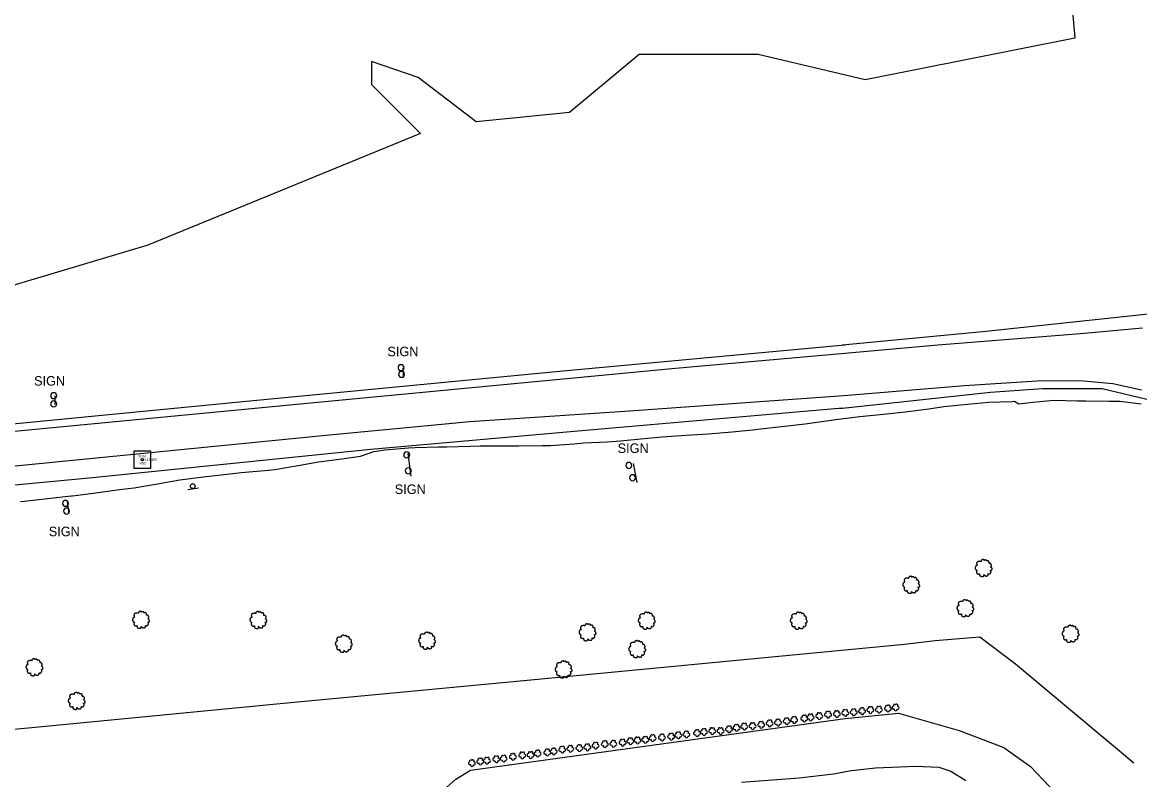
# Model space of a CAD drawing. Extents: x 1901471 to 1963503, y 756461 to 799997.
# Drawn here: x 1911553.6 to 1912023.9, y 761022.6 to 761341.4 of the extents above; entities that cross this region are included whole.
import ezdxf

# ---------------------------------------------------------------- set-up
doc = ezdxf.new("R2010")
doc.units = 0
for name, color, linetype in [('Default', 7, 'Continuous'), ('RD_DTM_BkLn1', 7, 'Continuous'), ('RD_EX_Bldg', 7, 'Continuous'), ('RD_EX_BldgApp', 7, 'Continuous'), ('RD_EX_Fence_Other', 7, 'Continuous'), ('RD_EX_H2O', 7, 'Continuous'), ('RD_EX_Road', 7, 'Continuous'), ('RD_EX_Road_txCode', 7, 'Continuous'), ('RD_EX_VEG', 7, 'Continuous'), ('RD_HC_Cl', 7, 'Continuous'), ('RD_HC_Survey', 7, 'Continuous'), ('RD_HC_txCode', 7, 'Continuous'), ('RD_SMD_Locator', 7, 'Continuous')]:
    doc.layers.add(name, color=color, linetype=linetype)

# ---------------------------------------------------------------- blocks, each defined once
blk = doc.blocks.new('T2')
at = {"layer": 'RD_EX_VEG'}
for points in [[(0.05, 7.21), (-0.25, 7.24), (-0.57, 7.14), (-0.82, 7.04), (-1.05, 6.96), (-1.27, 6.86), (-1.57, 6.69), (-1.8, 6.49), (-1.92, 6.24), (-1.97, 6.01), (-2.02, 5.74), (-2.02, 5.56), (-2.15, 5.54), (-2.3, 5.56), (-2.55, 5.64), (-2.8, 5.64), (-3.05, 5.64), (-3.4, 5.61), (-3.75, 5.61), (-4.02, 5.56), (-4.35, 5.51), (-4.72, 5.39), (-5.07, 5.26), (-5.37, 5.01), (-5.62, 4.54), (-5.75, 4.19), (-5.9, 3.94), (-5.75, 3.49), (-5.57, 3.14), (-5.55, 2.94), (-5.47, 2.52), (-5.37, 2.29), (-5.25, 2.09), (-5.32, 2.07), (-5.7, 2.02), (-6, 1.92), (-6.42, 1.69), (-6.64, 1.47), (-6.74, 1.14), (-6.77, 0.79), (-6.87, 0.59), (-6.94, 0.32), (-6.97, 0.24), (-7.02, -0.08), (-6.92, -0.53), (-6.89, -0.88), (-6.77, -1.11), (-6.62, -1.28), (-6.44, -1.53), (-6.05, -1.76), (-5.72, -1.86), (-5.52, -1.88), (-5.7, -2.38), (-5.75, -2.73), (-5.87, -3.13), (-5.87, -3.21), (-5.92, -3.68), (-5.77, -4.01), (-5.7, -4.38), (-5.52, -4.61), (-5.25, -4.91), (-4.92, -5.13), (-4.42, -5.26), (-4.02, -5.23), (-3.45, -5.06), (-3.2, -4.98), (-3.22, -5.16), (-3.2, -5.53), (-3.2, -5.96), (-3.05, -6.28), (-2.95, -6.56), (-2.8, -6.81), (-2.47, -7.03), (-2.07, -7.11), (-1.65, -7.26), (-1.2, -7.33), (-0.7, -7.36), (-0.1, -7.21), (0.18, -7.08), (0.28, -6.91), (0.48, -6.53), (0.43, -6.31), (0.45, -5.71), (0.55, -5.88), (0.73, -6.23), (1.23, -6.53), (1.63, -6.71), (2.1, -6.86), (2.4, -6.93), (2.88, -6.86), (3.25, -6.78), (3.63, -6.66), (3.93, -6.38), (4.1, -6.11), (4.15, -5.83), (4.23, -5.46), (4.28, -5.28)], [(4.28, -5.28), (4.2, -5.11), (4.15, -4.86), (4.23, -4.88), (4.4, -4.93), (4.68, -5.06), (4.9, -5.13), (5.23, -5.11), (5.5, -5.01), (5.95, -4.73), (6.22, -4.26), (6.5, -3.86), (6.57, -3.53), (6.52, -3.31), (6.5, -2.81), (6.3, -2.56), (6.25, -2.43), (6.15, -2.03), (6.22, -1.98), (6.5, -1.93), (6.87, -1.81), (7.15, -1.68), (7.37, -1.51), (7.45, -1.28), (7.42, -0.88), (7.47, -0.48), (7.4, -0.33), (7.3, -0.18), (7.22, 0.02), (7.07, 0.17), (6.97, 0.32), (6.87, 0.42), (6.75, 0.57), (6.57, 0.69), (6.42, 0.74), (6.37, 0.89), (6.52, 1.09), (6.57, 1.19), (6.6, 1.42), (6.82, 1.77), (6.87, 2.17), (6.82, 2.59), (6.77, 2.87), (6.62, 3.14), (6.42, 3.39), (6.3, 3.56), (6.12, 3.69), (5.8, 3.81), (5.55, 3.86), (5.2, 3.86), (5, 3.91), (5.03, 3.96), (5.03, 4.11), (5.03, 4.39), (4.95, 4.84), (4.8, 5.34), (4.8, 5.36), (4.7, 5.61), (4.48, 5.81), (4.3, 5.91), (4.1, 6.04), (3.85, 6.06), (3.55, 6.06), (3.28, 6.01), (3.08, 5.91), (2.9, 5.79), (2.83, 5.94), (2.73, 6.24), (2.68, 6.39), (2.53, 6.56), (2.3, 6.76), (1.85, 6.89), (1.23, 6.81), (0.93, 6.61), (0.78, 6.44), (0.73, 6.56), (0.53, 6.76), (0.43, 6.94), (0.25, 7.06), (0.1, 7.16), (0, 7.21)]]:
    blk.add_spline(points, degree=3, dxfattribs=at)
blk = doc.blocks.new('SB2')
at = {"layer": 'RD_EX_VEG'}
for centre, radius, start, end in [((-1.56, -0.16), 1.26, 96.45179, 294.73401), ((-0.72, 1.55), 1.08, 34.97629, 204.75602), ((1.05, 1.7), 0.995, 308.76261, 152.04674), ((1.84, -0.28), 1.22, 256.56668, 98.10463), ((0.25, -1.6), 1.32, 166.88266, 5.75893)]:
    blk.add_arc(centre, radius, start, end, dxfattribs=at)
blk = doc.blocks.new('SIGNPOST')
at = {"layer": 'Default'}
for start, end in [(90, 270), (270, 90)]:
    blk.add_arc((0, 0), 0.127, start, end, dxfattribs=at)
blk = doc.blocks.new('SIGN')
at = {"layer": 'RD_EX_BldgApp'}
blk.add_line((-4.52, -2.02), (4.48, -2.02), dxfattribs=at)
blk.add_circle((0, 0), 2, dxfattribs=at)

msp = doc.modelspace()

# ---------------------------------------------------------------- linework, layer by layer
at = {"layer": 'RD_DTM_BkLn1'}
for points in [[(1911659.88, 761153.18), (1911669.72, 761154.91), (1911678.21, 761156.4), (1911688.12, 761157.71), (1911695.98, 761158.75), (1911701.62, 761160.74), (1911706.22, 761161.47), (1911716.18, 761162.29), (1911718.95, 761162.52), (1911728.94, 761162.72), (1911732.15, 761162.78), (1911742.13, 761163.08), (1911746.35, 761163.21), (1911756.35, 761163.2), (1911762.54, 761163.2), (1911772.54, 761163.27), (1911775.88, 761163.29), (1911785.84, 761164.06), (1911789.81, 761164.36), (1911799.79, 761164.91), (1911805.35, 761165.22), (1911815.29, 761166.22), (1911822.91, 761167), (1911832.88, 761167.6), (1911842.39, 761168.18), (1911852.34, 761169.11), (1911862.29, 761170.03), (1911863.21, 761170.12), (1911873.14, 761171.31), (1911883.06, 761172.49), (1911886.06, 761172.85), (1911895.96, 761174.2), (1911906.1, 761175.58), (1911916.05, 761176.55), (1911925.23, 761177.45), (1911935.12, 761178.81), (1911941.43, 761179.67), (1911951.37, 761180.64), (1911960.3, 761181.51), (1911970.29, 761181.89), (1911971.21, 761181.93), (1911973.03, 761180.8), (1911978.98, 761181.5), (1911987.81, 761182.35), (1911997.8, 761182.16), (1912001.19, 761182.1), (1912011.18, 761182.03), (1912015.59, 761181.99), (1912024.5, 761180.87)], [(1911552.87, 761139.7), (1911554.34, 761139.87), (1911564.26, 761140.99), (1911574.19, 761142.1), (1911574.69, 761142.15), (1911584.59, 761143.44), (1911594.5, 761144.72), (1911600.71, 761145.53), (1911610.55, 761147.23), (1911619.95, 761148.86), (1911629.87, 761150.07), (1911639.79, 761151.29), (1911645.68, 761152.01), (1911655.63, 761152.83), (1911659.88, 761153.18)]]:
    msp.add_lwpolyline(points, dxfattribs=at)
at = {"layer": 'RD_EX_Bldg'}
for points in [[(1911714.11, 761192.5), (1911713.9, 761195.96)], [(1911567.49, 761180.52), (1911567.49, 761184.19)], [(1911717.35, 761150.39), (1911716.06, 761159.89)], [(1911812.36, 761147.8), (1911810.85, 761155.79)], [(1911573.32, 761134.63), (1911572.67, 761139.6)]]:
    msp.add_lwpolyline(points, dxfattribs=at)
at = {"layer": 'RD_EX_Fence_Other'}
for points in [[(1911301.9, 761016.76), (1911361.19, 761026.56), (1911419.09, 761032.24), (1911466.66, 761036.35), (1911557.62, 761044.66), (1911663.61, 761054.89), (1911770.66, 761064.95), (1911924.93, 761079.73), (1911937.87, 761081.21), (1911956.59, 761082.79), (1911971.63, 761071.42), (1912021.48, 761029.79)], [(1911763.4, 760914.3), (1911750.84, 760916.21), (1911744.62, 760921.26), (1911722.85, 760995.7), (1911722.85, 761003.37), (1911725.57, 761010.56), (1911730.04, 761017.56), (1911736.07, 761022.81), (1911742.29, 761026.69), (1911899.9, 761048.36), (1911922.46, 761050.69), (1911947.94, 761043.35), (1911966.73, 761036.22), (1911977.96, 761028.23), (1911993.72, 761011.61), (1911997.39, 761002.75), (1911997.82, 760995.2), (1911994.8, 760987.64), (1911989.62, 760981.81), (1911983.14, 760977.27), (1911976.23, 760974.03), (1911966.94, 760971.23), (1911949.45, 760965.61), (1911905.83, 760953.84)]]:
    msp.add_lwpolyline(points, dxfattribs=at)
at = {"layer": 'RD_EX_H2O'}
msp.add_lwpolyline([(1911856.34, 761021.65), (1911880.53, 761023.47), (1911895.01, 761025.08), (1911901.72, 761026.38), (1911902.64, 761026.54), (1911912.73, 761027.6), (1911929.56, 761028.37), (1911939.37, 761027.86), (1911944.43, 761026.16), (1911950.75, 761022.26)], dxfattribs=at)
at = {"layer": 'RD_EX_Road'}
for points in [[(1912072.27, 761284.55), (1912073.94, 761249.92), (1912071.95, 761235.72), (1912064.97, 761228.49), (1912046.04, 761220.52), (1911959.1, 761211.3), (1911898.88, 761205.6)], [(1910806.95, 760986.51), (1910899.81, 761023.81), (1910997.7, 761062.68), (1911080.96, 761091.36), (1911138.06, 761108.15), (1911210.76, 761126.27), (1911274.58, 761138.02), (1911355.92, 761149.66), (1911431.5, 761158.3), (1911541.39, 761168.49), (1911685.34, 761182.29), (1911828.58, 761195.85), (1911899.84, 761202.2), (1911938.91, 761205.69), (1911998.94, 761210.45), (1912025.07, 761212.82)], [(1910882.79, 761021.04), (1910921.3, 761035.52), (1910979.88, 761059.55), (1911049, 761083.58), (1911113.18, 761104.97), (1911182.95, 761123.73), (1911238.25, 761135.74), (1911300.45, 761145.95), (1911367.92, 761154.5), (1911431.77, 761161.25), (1911532.15, 761170.79), (1911649.32, 761182.15), (1911779.66, 761194.66), (1911899.79, 761205.68)], [(1910585.74, 760878.06), (1910710.5, 760928.56), (1910888.29, 761001.62), (1910940.6, 761022.74), (1910979.47, 761037.97), (1911045.69, 761063.88), (1911129.18, 761091.6), (1911194.2, 761107.91), (1911276.02, 761125.07), (1911337.2, 761133.46), (1911445.17, 761144.38), (1911566.34, 761156.26), (1911684.38, 761167.89), (1911741.97, 761173.41), (1911807.23, 761177.73), (1911899.39, 761184.42), (1911950.14, 761188.53), (1911980.8, 761190.47), (1911998.72, 761190.69), (1912012.54, 761189.39), (1912024.63, 761186.8)], [(1911897.49, 761178.91), (1911961.09, 761185.77), (1911983.01, 761187.26), (1912008.17, 761187.26), (1912029.35, 761182.28), (1912048.28, 761172.06), (1912063.23, 761159.36), (1912077.93, 761137.06), (1912083.66, 761120.12), (1912085.9, 761099.07), (1912090.39, 761029.31), (1912094.37, 760970.15), (1912097.86, 760918.95), (1912097.86, 760912.35), (1912095.12, 760847.08), (1912093.87, 760825.28), (1912094.12, 760802.11), (1912094.28, 760797.36)], [(1911898.8, 761179.02), (1911785.91, 761169.15), (1911700.34, 761161.58), (1911583.17, 761149.73), (1911418.28, 761134.1), (1911324.15, 761123.73), (1911252.4, 761112.21), (1911180.98, 761095.75), (1911047.68, 761055.44), (1910980.21, 761027.79), (1910849.63, 760977.02), (1910755.82, 760938.15), (1910677.81, 760906.77), (1910499.57, 760835.69), (1910338.5, 760760.54), (1910201.4, 760696.87), (1909857.87, 760545.92), (1909713.02, 760487.06), (1909551.94, 760422.89), (1909472.41, 760392.45), (1909224.63, 760297.56), (1909135.34, 760263.39), (1909100.59, 760249.47)]]:
    msp.add_lwpolyline(points, dxfattribs=at)
at = {"layer": 'RD_EX_VEG'}
msp.add_lwpolyline([(1911365.4, 761253.45), (1911526.14, 761364.2), (1911737.84, 761511.22), (1911890.73, 761612.17), (1911939.74, 761640.59), (1911963.26, 761618.05), (1911978.94, 761536.7), (1911996.58, 761334.8), (1911908.37, 761317.16), (1911863.29, 761327.94), (1911813.31, 761327.94), (1911783.9, 761303.44), (1911744.7, 761299.52), (1911720.2, 761318.14), (1911700.59, 761325), (1911700.59, 761315.2), (1911721.18, 761294.61), (1911606.51, 761247.57), (1911550.64, 761230.91), (1911510.46, 761233.85), (1911426.17, 761216.21), (1911373.24, 761194.64), (1911348.74, 761205.43), (1911355.6, 761230.91)], close=True, dxfattribs=at)
at = {"layer": 'RD_HC_Cl'}
for centre, radius, start, end in [((1905408.25, 771170.65), 11414.07, 290.89447, 304.008825), ((1905390.19, 771086.47), 11384.37, 290.903407, 304.008529), ((1905358.49, 771272.41), 11611.54, 290.901971, 304.0171)]:
    msp.add_arc(centre, radius, start, end, dxfattribs=at)
at = {"layer": 'RD_HC_Survey'}
msp.add_lwpolyline([(1911607.68, 761160.89), (1911600.61, 761160.89), (1911600.61, 761153.81), (1911607.68, 761153.81)], close=True, dxfattribs=at)
msp.add_circle((1911604.14, 761157.35), 0.5, dxfattribs=at)
at = {"layer": 'RD_SMD_Locator'}
msp.add_circle((1911604.14, 761157.35), 0.001, dxfattribs=at)

# ---------------------------------------------------------------- block references
at = {"layer": 'RD_EX_Bldg', "xscale": 9.84251968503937, "yscale": 9.84251968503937}
for p in [(1911713.03, 761196.06), (1911713.25, 761193.26), (1911566.84, 761184.29), (1911566.84, 761180.84), (1911715.41, 761159.35), (1911808.91, 761154.93), (1911716.06, 761152.66), (1911810.42, 761149.74), (1911571.81, 761138.95), (1911572.24, 761135.71)]:
    msp.add_blockref('SIGNPOST', p, dxfattribs=at)
at = {"layer": 'RD_EX_Bldg', "xscale": 0.5039370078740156, "yscale": 0.5039370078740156, "rotation": 9.293309}
msp.add_blockref('SIGN', (1911625.36, 761146.18), dxfattribs=at)
at = {"layer": 'RD_EX_VEG'}
for name, p, xscale, yscale in [('T2', (1911958.11, 761111.77), 0.4921259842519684, 0.4921259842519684), ('T2', (1911927.66, 761104.7), 0.4921259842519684, 0.4921259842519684), ('T2', (1911950.42, 761094.86), 0.4921259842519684, 0.4921259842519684), ('T2', (1911603.46, 761089.97), 0.4921259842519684, 0.4921259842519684), ('T2', (1911652.86, 761089.89), 0.4921259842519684, 0.4921259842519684), ('T2', (1911816.32, 761089.63), 0.4921259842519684, 0.4921259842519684), ('T2', (1911880.29, 761089.63), 0.4921259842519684, 0.4921259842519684), ('T2', (1911723.87, 761081.17), 0.4921259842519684, 0.4921259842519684), ('T2', (1911791.41, 761084.71), 0.4921259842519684, 0.4921259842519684), ('T2', (1911994.71, 761084.09), 0.4921259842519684, 0.4921259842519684), ('T2', (1911688.81, 761079.89), 0.4921259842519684, 0.4921259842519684), ('T2', (1911812.32, 761077.63), 0.4921259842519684, 0.4921259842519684), ('T2', (1911558.6, 761070), 0.4921259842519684, 0.4921259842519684), ('T2', (1911781.33, 761069.08), 0.4921259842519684, 0.4921259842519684), ('T2', (1911576.4, 761055.83), 0.4921259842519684, 0.4921259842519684), ('SB2', (1911892.7, 761050.07), 0.5019685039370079, 0.5019685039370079), ('SB2', (1911896.36, 761050.3), 0.5019685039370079, 0.5019685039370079), ('SB2', (1911899.89, 761050.78), 0.5019685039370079, 0.5019685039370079), ('SB2', (1911903.48, 761051.05), 0.5019685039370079, 0.5019685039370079), ('SB2', (1911907, 761051.52), 0.5019685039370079, 0.5019685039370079), ('SB2', (1911910.52, 761052), 0.5019685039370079, 0.5019685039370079), ('SB2', (1911914.12, 761052.2), 0.5019685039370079, 0.5019685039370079), ('SB2', (1911917.84, 761052.67), 0.5019685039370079, 0.5019685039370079), ('SB2', (1911921.1, 761053.08), 0.5019685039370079, 0.5019685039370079), ('SB2', (1911857.4, 761045.05), 0.5019685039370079, 0.5019685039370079), ('SB2', (1911860.92, 761045.25), 0.5019685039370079, 0.5019685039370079), ('SB2', (1911864.51, 761045.8), 0.5019685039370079, 0.5019685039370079), ('SB2', (1911868.1, 761046.41), 0.5019685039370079, 0.5019685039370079), ('SB2', (1911871.63, 761046.74), 0.5019685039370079, 0.5019685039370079), ('SB2', (1911875.29, 761047.29), 0.5019685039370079, 0.5019685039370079), ('SB2', (1911878.4, 761047.83), 0.5019685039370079, 0.5019685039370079), ('SB2', (1911882.67, 761048.44), 0.5019685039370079, 0.5019685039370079), ('SB2', (1911885.32, 761048.91), 0.5019685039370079, 0.5019685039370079), ('SB2', (1911888.98, 761049.46), 0.5019685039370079, 0.5019685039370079), ('SB2', (1911822.77, 761040.44), 0.5019685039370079, 0.5019685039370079), ('SB2', (1911826.63, 761040.78), 0.5019685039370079, 0.5019685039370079), ('SB2', (1911829.61, 761041.39), 0.5019685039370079, 0.5019685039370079), ('SB2', (1911833.07, 761041.73), 0.5019685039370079, 0.5019685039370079), ('SB2', (1911837.54, 761042.27), 0.5019685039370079, 0.5019685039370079), ('SB2', (1911840.46, 761042.75), 0.5019685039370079, 0.5019685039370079), ('SB2', (1911843.91, 761043.15), 0.5019685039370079, 0.5019685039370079), ('SB2', (1911847.44, 761043.15), 0.5019685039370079, 0.5019685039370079), ('SB2', (1911851.03, 761043.9), 0.5019685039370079, 0.5019685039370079), ('SB2', (1911854.15, 761044.51), 0.5019685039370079, 0.5019685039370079), ('SB2', (1911784.21, 761035.7), 0.5019685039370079, 0.5019685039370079), ('SB2', (1911788.01, 761035.97), 0.5019685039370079, 0.5019685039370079), ('SB2', (1911791.4, 761036.31), 0.5019685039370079, 0.5019685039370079), ('SB2', (1911794.85, 761037.05), 0.5019685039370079, 0.5019685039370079), ('SB2', (1911798.71, 761037.66), 0.5019685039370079, 0.5019685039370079), ('SB2', (1911802.31, 761037.8), 0.5019685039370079, 0.5019685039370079), ('SB2', (1911806.17, 761038.27), 0.5019685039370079, 0.5019685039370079), ('SB2', (1911809.49, 761038.88), 0.5019685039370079, 0.5019685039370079), ('SB2', (1911812.47, 761039.22), 0.5019685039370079, 0.5019685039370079), ('SB2', (1911815.72, 761039.49), 0.5019685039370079, 0.5019685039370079), ('SB2', (1911818.84, 761040.17), 0.5019685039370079, 0.5019685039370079), ('SB2', (1911753.04, 761031.29), 0.5019685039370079, 0.5019685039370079), ('SB2', (1911756.16, 761031.57), 0.5019685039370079, 0.5019685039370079), ('SB2', (1911760.02, 761032.31), 0.5019685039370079, 0.5019685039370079), ('SB2', (1911763.95, 761032.92), 0.5019685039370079, 0.5019685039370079), ('SB2', (1911767.48, 761033.06), 0.5019685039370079, 0.5019685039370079), ('SB2', (1911770.46, 761033.73), 0.5019685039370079, 0.5019685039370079), ('SB2', (1911774.52, 761034.14), 0.5019685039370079, 0.5019685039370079), ('SB2', (1911777.23, 761034.55), 0.5019685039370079, 0.5019685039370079), ('SB2', (1911780.76, 761035.36), 0.5019685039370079, 0.5019685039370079), ('SB2', (1911742.74, 761029.67), 0.5019685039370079, 0.5019685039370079), ('SB2', (1911746.27, 761030.35), 0.5019685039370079, 0.5019685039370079), ('SB2', (1911749.11, 761030.68), 0.5019685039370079, 0.5019685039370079)]:
    msp.add_blockref(name, p, dxfattribs=dict(at, xscale=xscale, yscale=yscale))

# ---------------------------------------------------------------- texts
at = {"layer": 'RD_EX_Road'}
for p in [(1911707.27, 761200.89), (1911558.57, 761188.52), (1911804.18, 761160.17), (1911710.37, 761142.91), (1911564.75, 761125.12)]:
    msp.add_text('SIGN', height=4, dxfattribs=at).set_placement(p)
at = {"layer": 'RD_EX_Road_txCode'}
msp.add_text('417.400', height=1, dxfattribs=at).set_placement((1911605.14, 761156.85))
at = {"layer": 'RD_HC_txCode'}
for s, p in [('9003', (1911602.44, 761158.35)), ('MSC', (1911602.83, 761155.35))]:
    msp.add_text(s, height=1, dxfattribs=at).set_placement(p)

doc.saveas('drawing.dxf')
